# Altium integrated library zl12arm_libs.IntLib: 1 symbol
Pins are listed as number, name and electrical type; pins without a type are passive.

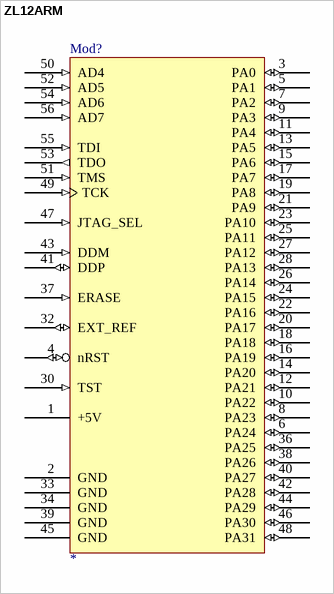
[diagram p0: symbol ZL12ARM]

## ZL12ARM
designator Mod?
www.btc.pl
footprint ZL12ARM
pins: 1 +5V (power), 2 GND (power), 3 PA0 (io), 4 nRST (io), 5 PA1 (io), 6 PA24 (io), 7 PA2 (io), 8 PA23 (io), 9 PA3 (io), 10 PA22 (io), 11 PA4 (io), 12 PA21 (io), 13 PA5 (io), 14 PA20 (io), 15 PA6 (io), 16 PA19 (io), 17 PA7 (io), 18 PA18 (io), 19 PA8 (io), 20 PA17 (io), 21 PA9 (io), 22 PA16 (io), 23 PA10 (io), 24 PA15 (io), 25 PA11 (io), 26 PA14 (io), 27 PA12 (io), 28 PA13 (io), 30 TST (in), 32 EXT_REF (io), 33 GND (power), 34 GND (power), 36 PA25 (io), 37 ERASE (in), 38 PA26 (io), 39 GND (power), 40 PA27 (io), 41 DDP (io), 42 PA28 (io), 43 DDM (in), 44 PA29 (io), 45 GND (power), 46 PA30 (io), 47 JTAG_SEL (in), 48 PA31 (io), 49 TCK (in), 50 AD4 (in), 51 TMS (in), 52 AD5 (in), 53 TDO (out), 54 AD6 (in), 55 TDI (in), 56 AD7 (in)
